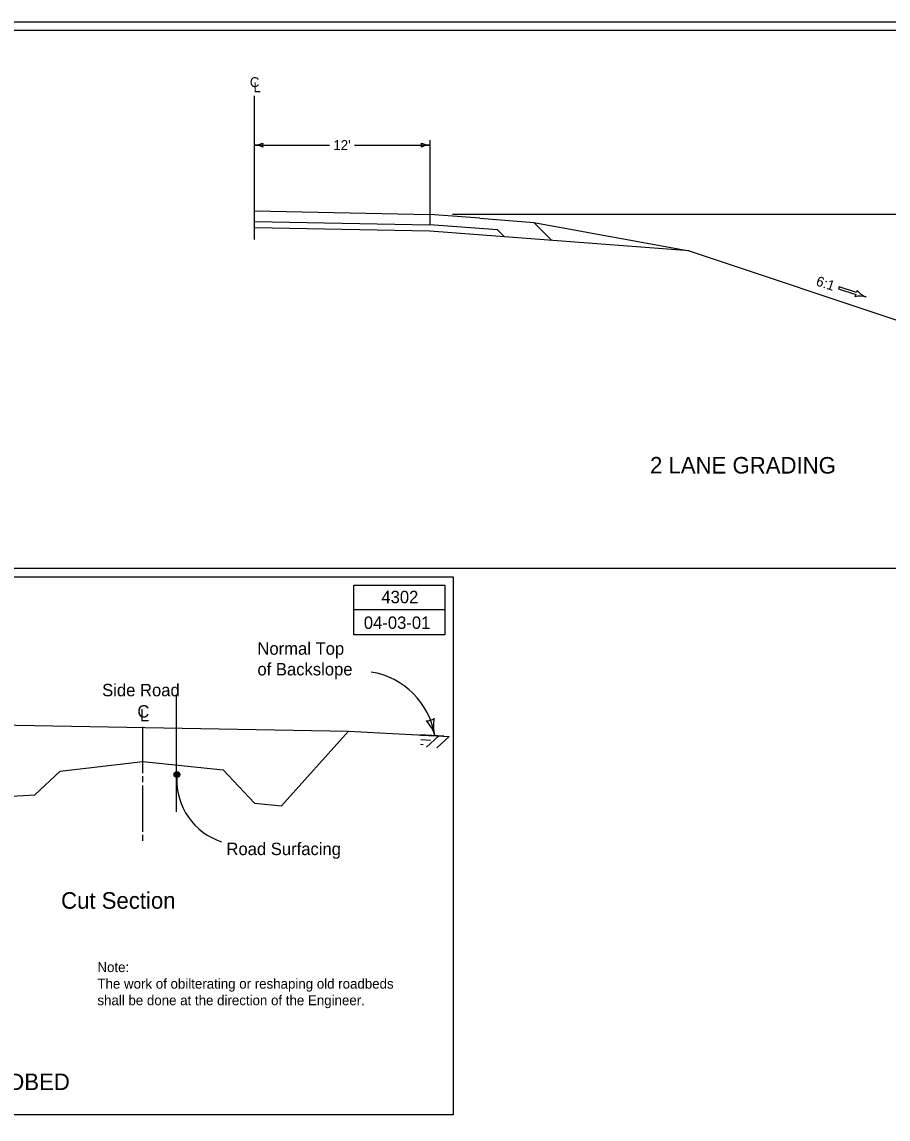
# Model space of a CAD drawing. Extents: x 10133 to 81668, y 7924 to 11018.
# Drawn here: x 11172 to 12218, y 8619 to 9944 of the extents above; entities that cross this region are included whole.
import ezdxf

# ---------------------------------------------------------------- set-up
doc = ezdxf.new("R2010")
doc.units = 0
for name, color, linetype in [('Default', 7, 'Continuous'), ('dsnCellElements', 7, 'Continuous'), ('DsnShtMinorGrid06', 7, 'Continuous'), ('DsnShtMinorGrid08', 7, 'Continuous'), ('DsnShtMinorGrid09', 7, 'Continuous'), ('DsnShtMinorGrid10', 7, 'Continuous'), ('DsnShtMinorGrid12', 7, 'Continuous'), ('dsnStdNameDate', 7, 'Continuous'), ('Level 10', 7, 'Continuous'), ('Level 4', 7, 'Continuous'), ('Level 5', 7, 'Continuous'), ('Level 6', 7, 'Continuous'), ('Level 7', 7, 'Continuous'), ('Level 8', 7, 'Continuous'), ('SheetAddendum', 7, 'Continuous'), ('SheetBorder', 7, 'Continuous'), ('ShtPlotIdentification', 7, 'Continuous')]:
    doc.layers.add(name, color=color, linetype=linetype)

msp = doc.modelspace()

# ---------------------------------------------------------------- linework, layer by layer
at = {"layer": 'Default'}
for p, q in [((11452.5, 9715.8), (11664, 9711.5)), ((11452.5, 9703.2), (11664, 9699)), ((11724.5, 9706.9), (11664, 9711.5)), ((11745.9, 9692.8), (11664, 9699)), ((11724.5, 9706.9), (11789.7, 9702)), ((11789.7, 9702), (11977.5, 9667.4)), ((11789.7, 9702), (11811.6, 9680)), ((11745.9, 9692.8), (11754.2, 9684.4))]:
    msp.add_line(p, q, dxfattribs=at)
at = {"layer": 'dsnCellElements'}
msp.add_line((11358, 9131.6), (11358, 8990.1), dxfattribs=at)
for points in [[(10956, 9100.1), (11066, 9096.7), (11152.4, 9008.5), (11187.1, 9010.5), (11217.9, 9039), (11317.8, 9050.7), (11414.7, 9040.8), (11452.3, 9000.4), (11485.2, 8997.3), (11565.8, 9087.3), (11687.7, 9081.1)], [(11681.2, 9081.4), (11652.3, 9082.9)], [(11681.2, 9081.4), (11653.5, 9082.8)], [(11653.5, 9082.8), (11681.2, 9081.4)]]:
    msp.add_lwpolyline(points, dxfattribs=at)
at = {"layer": 'DsnShtMinorGrid06'}
for p, q in [((11452.5, 9681.4), (11452.5, 9854.8)), ((11452.5, 9795.3), (11543.1, 9795.3)), ((11573.4, 9795.3), (11664, 9795.3)), ((11664, 9801.3), (11664, 9699)), ((12397.7, 9711.5), (11691.5, 9711.5))]:
    msp.add_line(p, q, dxfattribs=at)
for centre, radius, start, end in [((11452.5, 9816.6), 21.3, 270, 298.0725), ((11452.5, 9774.1), 21.3, 61.9275, 90), ((11470.3, 9795.3), 8.21, 162.2666, 197.7334), ((11646.2, 9795.3), 8.21, 342.2666, 17.7333), ((11664, 9816.6), 21.3, 241.9275, 270), ((11664, 9774.1), 21.3, 90, 118.0725)]:
    msp.add_arc(centre, radius, start, end, dxfattribs=at)
at = {"layer": 'DsnShtMinorGrid08'}
msp.add_lwpolyline([(10147.5, 9934), (13252.5, 9934), (13252.5, 9284), (10147.5, 9284), (10147.5, 9934)], dxfattribs=at)
at = {"layer": 'DsnShtMinorGrid09'}
for p, q in [((12158.4, 9624), (12157.7, 9621.8)), ((12157.7, 9621.8), (12178.5, 9614.8)), ((12179.3, 9617.1), (12158.4, 9624)), ((12180.2, 9619.7), (12179.3, 9617.1)), ((12178.5, 9614.8), (12177.6, 9612.1)), ((12191, 9611.9), (12191, 9611.9))]:
    msp.add_line(p, q, dxfattribs=at)
for centre, start, end in [((12200.2, 9636), 219.183, 249.213), ((12183.9, 9587.1), 73.917, 103.947)]:
    msp.add_arc(centre, 25.8, start, end, dxfattribs=at)
at = {"layer": 'DsnShtMinorGrid10'}
msp.add_line((11977.5, 9667.4), (12245, 9578.2), dxfattribs=at)
at = {"layer": 'DsnShtMinorGrid12'}
for p, q in [((11664, 9691.3), (11452.5, 9695.5)), ((11977.5, 9667.4), (11664, 9691.3))]:
    msp.add_line(p, q, dxfattribs=at)
at = {"layer": 'Level 10'}
for centre, radius, start, end in [((11578.6, 9067.2), 92.8, 9.2544, 80.8486), ((11436.5, 9028), 77.8, 177.31, 252.2589)]:
    msp.add_arc(centre, radius, start, end, dxfattribs=at)
at = {"layer": 'Level 4'}
msp.add_lwpolyline([(11682.5, 9264), (11682.5, 9204), (11572.5, 9204), (11572.5, 9264), (11682.5, 9264), (11682.5, 9234), (11572.5, 9234)], dxfattribs=at)
at = {"layer": 'Level 5'}
for points in [[(10147.5, 9274), (11692.5, 9274), (11692.5, 8624), (10147.5, 8624), (10147.5, 9274)], [(11358.6, 9032), (11359.7, 9032.5), (11361.6, 9033.1), (11361.9, 9034.9), (11361.7, 9036.6), (11360.5, 9038.1), (11358.8, 9037.9), (11356.9, 9037.7), (11356, 9036.2), (11355.9, 9034.7), (11357, 9032.6), (11358.3, 9032.5), (11360.1, 9032.9), (11361.7, 9034.1), (11361.6, 9035.9), (11360.4, 9037.3), (11358.8, 9037.4), (11356.9, 9037.1), (11356.7, 9036), (11356.3, 9034.8), (11357.1, 9033.3), (11358.5, 9033.3), (11360, 9033.6), (11361.1, 9034.4), (11360.6, 9035.9), (11359.4, 9036.8), (11357.9, 9036.9), (11357.5, 9036.1), (11357, 9035.1), (11357.7, 9033.9), (11358.9, 9033.6), (11359.9, 9034.2), (11360, 9035.3), (11359.4, 9036.1), (11358.4, 9036.4), (11357.9, 9036), (11357.6, 9035.3), (11358.1, 9034.4), (11358.9, 9034.2), (11359.6, 9034.7), (11359.5, 9035.3), (11358.9, 9035.7), (11358.2, 9035.7), (11358.2, 9035.1), (11358.9, 9034.9)]]:
    msp.add_lwpolyline(points, dxfattribs=at)
msp.add_circle((11358.8, 9035.2), 3.5, dxfattribs=at)
for centre, radius, start, end in [((11660.4, 9116.4), 16.4, 268.172, 303.6387), ((11629.3, 9070.5), 42.5, 15.9054, 43.9779), ((11711.1, 9093.8), 42.5, 167.8329, 195.9054)]:
    msp.add_arc(centre, radius, start, end, dxfattribs=at)
at = {"layer": 'SheetAddendum'}
for p, q in [((11675.1, 9081.7), (11660.2, 9068.3)), ((11687.5, 9080.9), (11672.7, 9067.5))]:
    msp.add_line(p, q, dxfattribs=at)
for points in [[(11653.2, 9077.4), (11665.2, 9076.8)], [(11652.9, 9071.6), (11656.2, 9071.4)]]:
    msp.add_lwpolyline(points, dxfattribs=at)
at = {"layer": 'SheetBorder'}
msp.add_lwpolyline([(10132.5, 9944), (13267.5, 9944), (13267.5, 7924), (10132.5, 7924)], close=True, dxfattribs=at)
at = {"layer": 'ShtPlotIdentification'}
msp.add_line((11066, 9096.7), (11565.8, 9087.3), dxfattribs=at)
for points in [[(11317.4, 9092.7), (11317.4, 9036.9)], [(11317.4, 9033.1), (11317.4, 9025.7)], [(11317.4, 9022), (11317.4, 8966.1)], [(11317.4, 8962.4), (11317.4, 8954.9)]]:
    msp.add_lwpolyline(points, dxfattribs=at)
msp.add_arc((11436.5, 9028), 77.8, 174.663, 174.8906, dxfattribs=at)

# ---------------------------------------------------------------- texts
at = {"layer": 'DsnShtMinorGrid06'}
msp.add_text("12'", height=12, dxfattribs=at).set_placement((11547.7, 9789.3))
at = {"layer": 'DsnShtMinorGrid09'}
for s, p in [('C', (11446.8, 9865.3)), ('L', (11451.2, 9859.1))]:
    msp.add_text(s, height=12, dxfattribs=at).set_placement(p)
for s, height, rotation, p in [('6:1', 12, 341.565, (12129.6, 9626.1)), ('2 LANE GRADING', 20, 359.9583, (11930.1, 9398.7))]:
    msp.add_text(s, height=height, rotation=rotation, dxfattribs=at).set_placement(p)
at = {"layer": 'dsnStdNameDate'}
for s, p in [('4302', (11605.7, 9242)), ('04-03-01', (11584.5, 9211))]:
    msp.add_text(s, height=15, dxfattribs=at).set_placement(p)
at = {"layer": 'Level 6'}
for s, p in [('Cut Section', (11218.9, 8873)), ('TYPICAL DETAILS FOR OBLITERATION EXISTING ROADBED', (10459.7, 8654))]:
    msp.add_text(s, height=19.999, dxfattribs=at).set_placement(p)
at = {"layer": 'Level 7'}
for s, p in [('Normal Top ', (11456, 9179.8)), ('of Backslope', (11456, 9154.8)), ('Side Road', (11268.5, 9129.6)), ('C', (11311, 9103.9)), ('L', (11314.1, 9099.2)), ('Road Surfacing', (11418.6, 8937.8))]:
    msp.add_text(s, height=15, dxfattribs=at).set_placement(p)
at = {"layer": 'Level 8'}
for s, p in [('Note:', (11262.8, 8796.5)), ('The work of obilterating or reshaping old roadbeds ', (11262.8, 8776.5)), ('shall be done at the direction of the Engineer.', (11262.8, 8756.5))]:
    msp.add_text(s, height=12, dxfattribs=at).set_placement(p)

doc.saveas('drawing.dxf')
